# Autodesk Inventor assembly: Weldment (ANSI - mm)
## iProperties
Length Units: 11269
Angle Units: 11283
Time Units: 11279
Mass Units: 11290
Length Display Precision: 3
Angle Display Precision: 2
Part Number: Weldment (ANSI - mm)
Document SubType Name: Weldment
Created: 2002-06
Designer: smithga
Part Number: chapter8-2
Created: 2002-11
Designer: Elise Moss
Control State: 0
Master: False
Shininess: 64.0
Angle Units: 11279
Time Units: 11290
Mass Units: 11283
Compacted: True
Density: 0.0
Volumn: 0.0
Area: 0.0
PropertySet Name: Model Information
Author: Elise Moss
